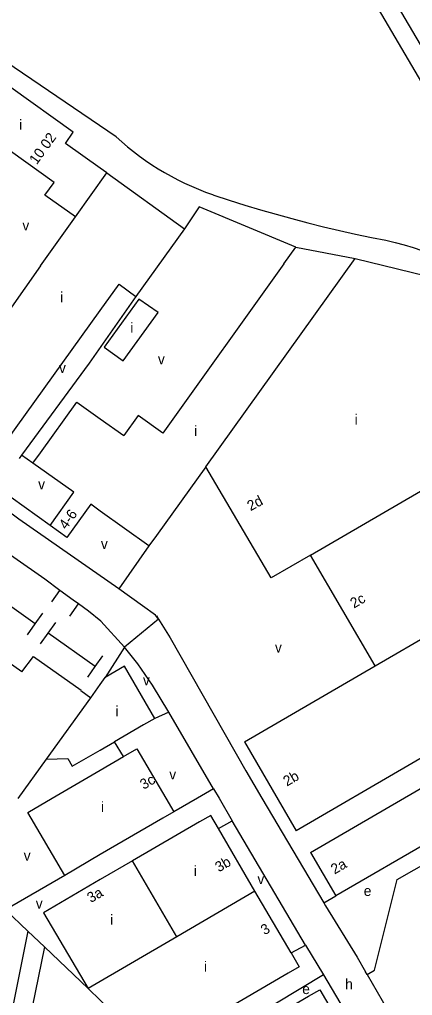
# Model space of a CAD drawing. Extents: x 157699 to 159683, y 381451 to 383293.
# Drawn here: x 158968.6 to 159121.6, y 382356.5 to 382736.7 of the extents above; entities that cross this region are included whole.
import ezdxf

# ---------------------------------------------------------------- set-up
doc = ezdxf.new("R2010")
doc.units = 0
for name, color, linetype in [('BLT_Basislijn', 7, 'Continuous'), ('BLT_Bebouwing', 7, 'Continuous'), ('BLT_Centroide', 7, 'Continuous'), ('BLT_Huisnummer', 7, 'Continuous'), ('BLT_Huisnummer_reeks', 7, 'Continuous'), ('BLT_Onderverdeling_panden', 7, 'Continuous'), ('BLT_Vlakafsluiter', 7, 'Continuous')]:
    doc.layers.add(name, color=color, linetype=linetype)

msp = doc.modelspace()

# ---------------------------------------------------------------- linework, layer by layer
at = {"layer": 'BLT_Basislijn'}
for p, q in [((159081.87, 382786.07), (159135.33, 382694.59)), ((159006.18, 382690.97), (158919.5, 382750)), ((158969.39, 382567.03), (158968.39, 382565.68)), ((158973.82, 382563.86), (158969.39, 382567.03)), ((158980.45, 382539.61), (158960.07, 382554.19)), ((158974.65, 382501.24), (158928.33, 382533.94)), ((159018.99, 382531.69), (159007.23, 382514.92)), ((158981.18, 382509.9), (158984.3, 382514.32)), ((159016.52, 382508.32), (159007.23, 382514.92)), ((158988.18, 382504.3), (158991.54, 382509.06)), ((158974.65, 382501.24), (158977.61, 382505.42)), ((159021.89, 382504.56), (159022.74, 382503.17)), ((158971.7, 382497.05), (158974.65, 382501.24)), ((158979.7, 382497.66), (158982.66, 382501.84)), ((158976.75, 382493.47), (158979.7, 382497.66)), ((158998.07, 382484.69), (158979.7, 382497.66)), ((159009.4, 382492.24), (159001.93, 382480.43)), ((158998.07, 382484.69), (159001.02, 382488.88)), ((158995.11, 382480.51), (158998.07, 382484.69)), ((159026.74, 382466.89), (159021.24, 382464.47)), ((159044.17, 382436.98), (159026.74, 382466.89)), ((159009.1, 382449.63), (159005.53, 382455.33)), ((159046.03, 382421.49), (159051.36, 382424.52)), ((159080, 382376.11), (159051.36, 382424.52)), ((158986.18, 382403.27), (158963.05, 382389.93)), ((159087.08, 382392.58), (159091.79, 382395.35)), ((158971.87, 382381.61), (158978.31, 382375.44)), ((158978.31, 382375.44), (158995.24, 382359.2)), ((159074.38, 382373.05), (159080, 382376.11)), ((159080, 382376.11), (159086.9, 382364.52)), ((159103.9, 382364.71), (159103.3, 382365.76)), ((159086.9, 382364.52), (159026.81, 382328.36)), ((159103.9, 382364.71), (159158.8, 382270.22))]:
    msp.add_line(p, q, dxfattribs=at)
for points in [[(159141.7, 382698.15), (159091.12, 382784.18)], [(159006.18, 382690.97), (159008.37, 382689.01), (159010.61, 382687.11), (159012.91, 382685.27), (159015.25, 382683.5), (159017.64, 382681.79), (159020.08, 382680.15), (159022.56, 382678.57), (159025.08, 382677.07), (159027.65, 382675.63), (159030.25, 382674.26), (159032.88, 382672.96), (159035.56, 382671.74), (159038.26, 382670.59), (159040.99, 382669.51), (159043.76, 382668.51), (159044.2, 382668.35)], [(159044.2, 382668.35), (159050.24, 382666.36), (159056.31, 382664.44), (159062.41, 382662.6), (159068.53, 382660.83), (159074.67, 382659.14), (159080.83, 382657.53), (159087.01, 382656), (159093.21, 382654.54), (159099.42, 382653.16), (159105.66, 382651.86), (159111.27, 382650.77)], [(159076.18, 382648.07), (159038.51, 382663.81), (159032.77, 382655.11)], [(159111.27, 382650.77), (159114.81, 382649.87), (159118.33, 382648.9), (159121.83, 382647.85), (159125.3, 382646.72), (159128.75, 382645.52), (159130.64, 382644.82)], [(159013.9, 382628.87), (158995.73, 382602.82), (158969.39, 382567.03)], [(158984.3, 382514.32), (158978.4, 382518.63), (158932.64, 382550.68)], [(159007.23, 382514.92), (158968.3, 382542.05), (158957.06, 382550.35)], [(158989.45, 382510.57), (158984.3, 382514.32)], [(158991.54, 382509.06), (158989.45, 382510.57)], [(159009.4, 382492.24), (159000.23, 382502.27), (158995.47, 382506.21), (158991.54, 382509.06)], [(159022.74, 382503.17), (159021.58, 382504.72), (159016.52, 382508.32)], [(159022.74, 382503.17), (159027.21, 382495.85), (159056.65, 382444.02), (159062.97, 382433.33), (159087.08, 382392.58)], [(159026.74, 382466.89), (159020.41, 382477.35), (159014.68, 382485.71), (159009.4, 382492.24)], [(159044.17, 382436.98), (159037.93, 382433.33), (159028.63, 382428.07)], [(159044.17, 382436.98), (159046.28, 382433.33), (159051.36, 382424.52)], [(159103.9, 382364.71), (159106.84, 382366.39), (159115.66, 382401.7), (159147.89, 382420.05)], [(159087.08, 382392.58), (159087.76, 382391.42), (159100, 382371.43), (159103.3, 382365.76)], [(158978.31, 382375.44), (158972.33, 382346.27), (158956.46, 382266.56)], [(159086.9, 382364.52), (159100, 382342.33), (159119.07, 382310.05)]]:
    msp.add_lwpolyline(points, dxfattribs=at)
at = {"layer": 'BLT_Bebouwing'}
for p, q in [((158982, 382673.26), (158953.34, 382693.76)), ((159002.59, 382676.93), (159032.77, 382655.11)), ((158976.73, 382640.78), (158990.36, 382659.84)), ((159032.77, 382655.11), (159013.9, 382628.87)), ((159071.44, 382641.53), (159076.18, 382648.07)), ((159076.18, 382648.07), (159099.29, 382643.64)), ((159041.19, 382562.45), (159099.29, 382643.64)), ((159071.44, 382641.53), (159024.44, 382575.57)), ((158989.68, 382552.52), (158973.82, 382563.86)), ((158980.45, 382539.61), (158989.68, 382552.52)), ((159107.07, 382484.9), (159081.88, 382528.05)), ((158969.49, 382482.53), (158974.02, 382488.61)), ((159056.13, 382455.31), (159107.07, 382484.9)), ((159056.13, 382455.31), (159076.33, 382420.7)), ((158968.06, 382433.23), (158979.04, 382448.6)), ((159144.4, 382425.95), (159091.79, 382395.35)), ((159060.27, 382397.17), (159046.03, 382421.49)), ((159081.93, 382412.26), (159091.79, 382395.35)), ((159074.38, 382373.05), (159060.27, 382397.17)), ((158963.05, 382389.93), (158971.87, 382381.61)), ((158971.87, 382381.61), (158952.45, 382285.12))]:
    msp.add_line(p, q, dxfattribs=at)
for points in [[(159002.59, 382676.93), (159000.04, 382678.78), (158986.47, 382688.48), (158989.52, 382692.77), (158965.21, 382710.22), (158962.04, 382705.95)], [(158990.36, 382659.84), (158978.48, 382668.34), (158982, 382673.26)], [(159099.29, 382643.64), (159132.19, 382635.51), (159166.39, 382577.3)], [(158976.73, 382640.78), (158958.31, 382614.68)], [(158958.99, 382567.09), (158963.95, 382574.02), (158964.38, 382573.71), (158967.29, 382577.78), (158999.92, 382623.41), (159007.36, 382633.57), (159013.9, 382628.87)], [(158973.82, 382563.86), (158976.73, 382567.92), (158990.87, 382587.7), (158999.99, 382581.17), (159009.17, 382574.66)], [(159024.44, 382575.57), (159014.74, 382582.48), (159009.17, 382574.66)], [(159041.19, 382562.45), (159021.89, 382535.76), (159018.99, 382531.69)], [(159081.88, 382528.05), (159066.56, 382519.16), (159041.19, 382562.45)], [(159018.99, 382531.69), (159000, 382545.22), (158996.28, 382547.87), (158987.02, 382534.92), (158980.45, 382539.61)], [(158969.49, 382482.53), (158923.83, 382514.91)], [(159211.48, 382499.28), (159076.33, 382420.7)], [(158974.02, 382488.61), (158992.56, 382475.43), (158992.47, 382475.29), (158996.32, 382472.49)], [(159081.93, 382412.26), (159216.55, 382490.54)], [(159021.24, 382464.47), (159009.41, 382484.79), (159001.93, 382480.43)], [(158996.32, 382472.49), (159000, 382477.7), (159001.93, 382480.43)], [(159021.24, 382464.47), (159016.91, 382461.96), (159005.53, 382455.33)], [(158989.13, 382445.79), (159000, 382452.12), (159005.53, 382455.33)], [(159009.1, 382449.63), (159009.93, 382450.11), (159014.24, 382452.64), (159025.55, 382433.33), (159028.63, 382428.07)], [(158986.18, 382403.27), (158971.82, 382427.77), (158981.32, 382433.33), (159000.01, 382444.29), (159009.1, 382449.63)], [(158979.04, 382448.6), (158987.4, 382448.76), (158989.13, 382445.79)], [(159028.63, 382428.07), (159024.32, 382425.54), (158999.99, 382411.37), (158986.18, 382403.27)], [(159046.03, 382421.49), (159043.02, 382426.65), (159038.69, 382424.13), (159012.54, 382408.92)], [(159012.55, 382408.92), (158999.99, 382401.62), (158977.96, 382388.71), (158995.24, 382359.2)], [(159074.38, 382373.05), (159077.52, 382367.68), (159073.21, 382365.16), (159020.64, 382334.39)], [(158995.24, 382359.2), (159000.07, 382354.49), (159004.34, 382350.32)], [(159037.04, 382330.34), (159081.15, 382356.17), (159085.47, 382358.7), (159100, 382333.88), (159113.82, 382310.27), (159101.57, 382303.09), (159106.07, 382295.4)]]:
    msp.add_lwpolyline(points, dxfattribs=at)
msp.add_lwpolyline([(159015.07, 382627.75), (159001.57, 382609.06), (159008.95, 382603.73), (159022.56, 382622.57)], close=True, dxfattribs=at)
at = {"layer": 'BLT_Onderverdeling_panden'}
for p, q in [((158990.36, 382659.84), (159002.59, 382676.93)), ((159081.88, 382528.05), (159166.39, 382577.3)), ((159107.07, 382484.9), (159191.55, 382534.13)), ((158979.04, 382448.6), (158996.32, 382472.49)), ((159029.83, 382379.4), (159012.55, 382408.92)), ((159060.27, 382397.17), (159029.83, 382379.39)), ((159029.83, 382379.4), (158995.24, 382359.2))]:
    msp.add_line(p, q, dxfattribs=at)
at = {"layer": 'BLT_Vlakafsluiter'}
msp.add_line((159022.74, 382503.17), (159009.4, 382492.24), dxfattribs=at)

# ---------------------------------------------------------------- texts
at = {"layer": 'BLT_Centroide'}
for s, p in [('i', (158968.4, 382693.75)), ('v', (158969.68, 382654.54)), ('i', (158984.36, 382626.56)), ('i', (159011.7, 382614.67)), ('v', (159022.47, 382602.42)), ('v', (158983.94, 382599.04)), ('i', (159099.06, 382578.9)), ('i', (159036.56, 382574.47)), ('v', (158975.83, 382553.73)), ('v', (159000.27, 382530.47)), ('v', (159068.05, 382490.1)), ('v', (159016.64, 382477.38)), ('i', (159005.94, 382465.28)), ('v', (159026.89, 382440.65)), ('i', (159000.29, 382427.97)), ('v', (158970.21, 382409.01)), ('i', (159036.42, 382403.03)), ('v', (159061.23, 382399.9)), ('e', (159102.63, 382395.26)), ('v', (158974.91, 382390.34)), ('i', (159003.88, 382384.06)), ('i', (159040.38, 382365.78)), ('h', (159095.4, 382358.94)), ('e', (159078.67, 382357.05))]:
    msp.add_text(s, height=4, dxfattribs=at).set_placement(p)
at = {"layer": 'BLT_Huisnummer'}
for s, rotation, p in [('10 02', 54.2287, (158975.27, 382679.93)), ('2d', 28.4265, (159058.55, 382545.14)), ('2c', 30.1399, (159098.79, 382507.21)), ('3c', 30.184, (159016.93, 382436.6)), ('2b', 30.1752, (159072.69, 382437.86)), ('3b', 30.3392, (159046.19, 382404.41)), ('2a', 30.1765, (159091.25, 382403.59)), ('3a', 30.3709, (158996.35, 382392.46)), ('3', 30.3396, (159063.97, 382379.9))]:
    msp.add_text(s, height=4, rotation=rotation, dxfattribs=at).set_placement(p)
at = {"layer": 'BLT_Huisnummer_reeks'}
msp.add_text('4-6', height=4, rotation=54.4265, dxfattribs=at).set_placement((158986.79, 382537.77))

doc.saveas('drawing.dxf')
